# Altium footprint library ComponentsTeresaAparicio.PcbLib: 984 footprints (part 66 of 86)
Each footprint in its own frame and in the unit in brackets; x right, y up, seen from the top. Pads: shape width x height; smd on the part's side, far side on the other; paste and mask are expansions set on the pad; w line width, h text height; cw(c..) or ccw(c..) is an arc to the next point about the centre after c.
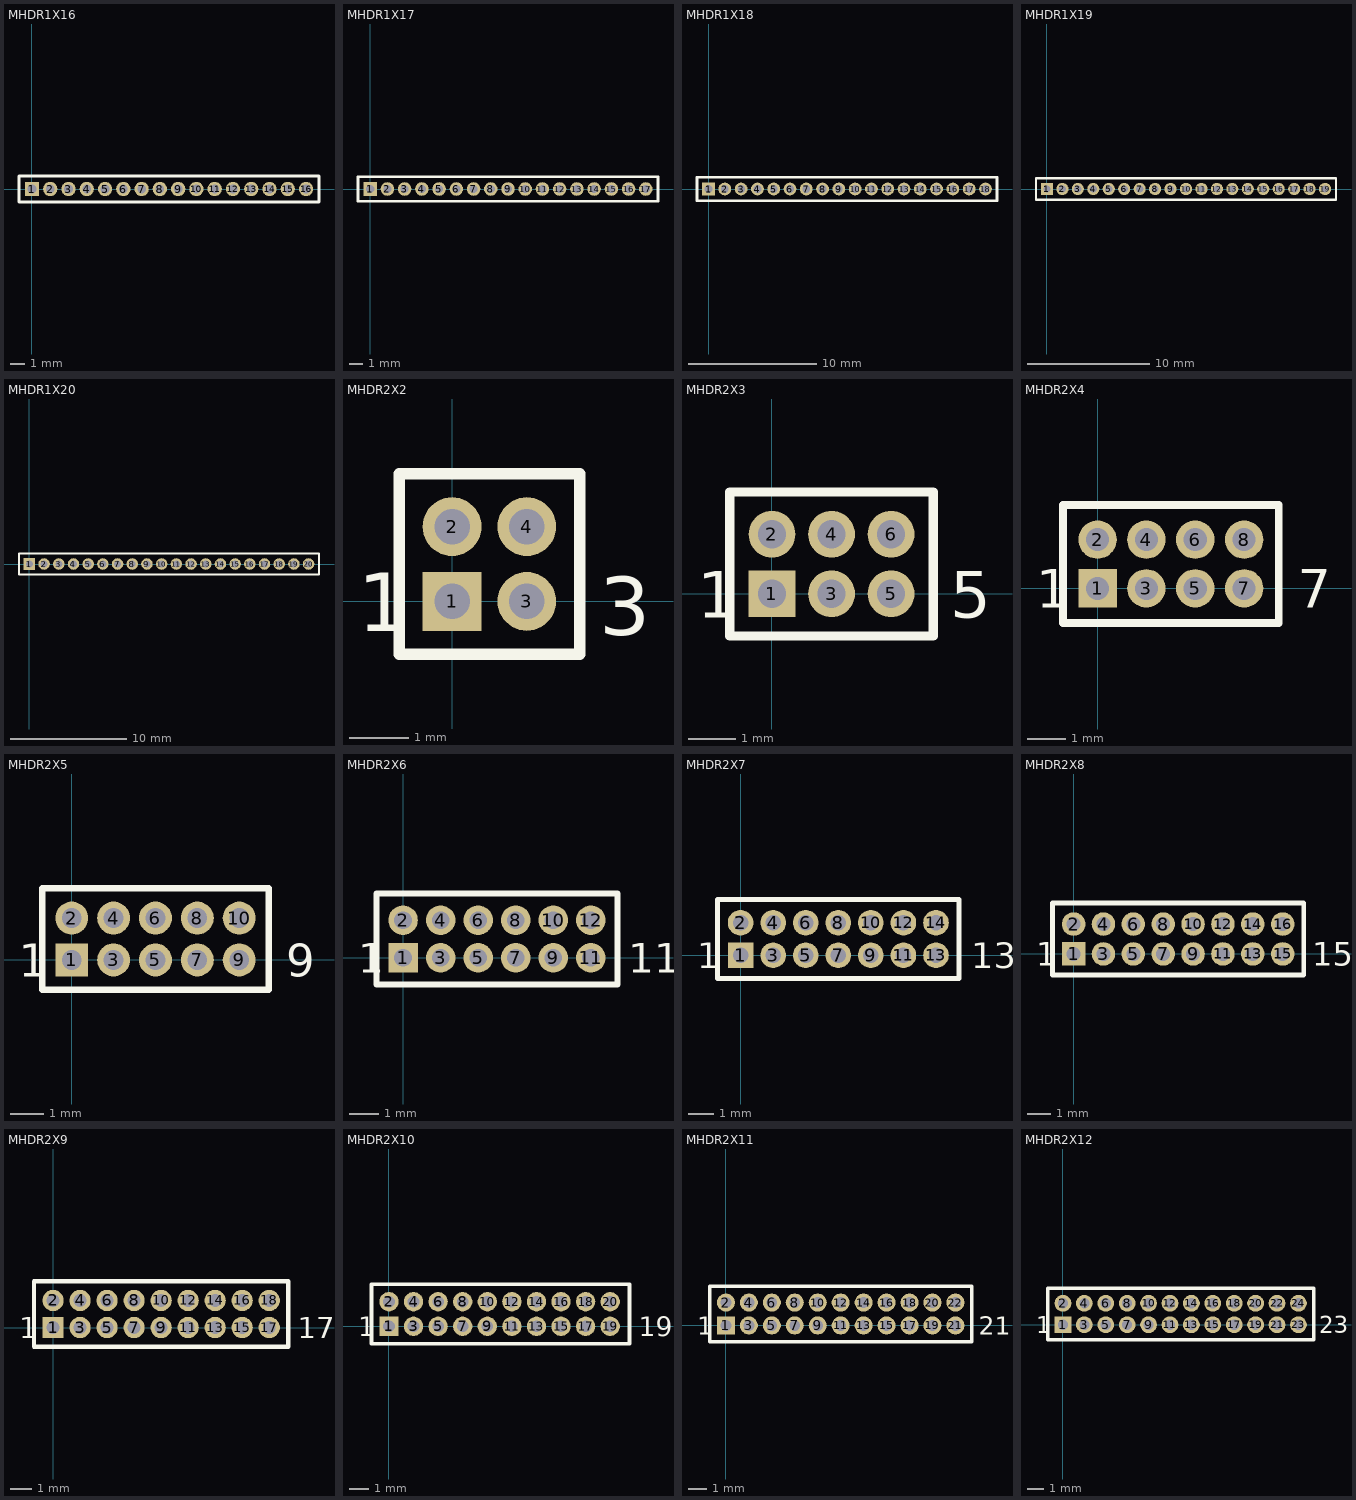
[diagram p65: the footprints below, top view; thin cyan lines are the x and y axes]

## MHDR1X16 [mm] "Connector; Header; 16 Position"
pads (16):
  rect 1x1 hole 0.6: 1(0,0)
  round 1 hole 0.6: 2(1.27,0) 3(2.54,0) 4(3.81,0) 5(5.08,0) 6(6.35,0) 7(7.62,0) 8(8.89,0) 9(10.16,0) 10(11.43,0) 11(12.7,0) 12(13.97,0) 13(15.24,0) 14(16.51,0) 15(17.78,0) 16(19.05,0)
Top Overlay:
  lines w0.2: -0.9,-0.9 19.95,-0.9 19.95,0.9 -0.9,0.9 -0.9,-0.9

## MHDR1X17 [mm] "Connector; Header; 17 Position"
pads (17):
  rect 1x1 hole 0.6: 1(0,0)
  round 1 hole 0.6: 2(1.27,0) 3(2.54,0) 4(3.81,0) 5(5.08,0) 6(6.35,0) 7(7.62,0) 8(8.89,0) 9(10.16,0) 10(11.43,0) 11(12.7,0) 12(13.97,0) 13(15.24,0) 14(16.51,0) 15(17.78,0) 16(19.05,0) 17(20.32,0)
Top Overlay:
  lines w0.2: -0.9,-0.9 -0.9,0.9 21.22,0.9 21.22,-0.9 -0.9,-0.9

## MHDR1X18 [mm] "Connector; Header; 18 Position"
pads (18):
  rect 1x1 hole 0.6: 1(0,0)
  round 1 hole 0.6: 2(1.27,0) 3(2.54,0) 4(3.81,0) 5(5.08,0) 6(6.35,0) 7(7.62,0) 8(8.89,0) 9(10.16,0) 10(11.43,0) 11(12.7,0) 12(13.97,0) 13(15.24,0) 14(16.51,0) 15(17.78,0) 16(19.05,0) 17(20.32,0) 18(21.59,0)
Top Overlay:
  lines w0.2: -0.9,-0.9 22.49,-0.9 22.49,0.9 -0.9,0.9 -0.9,-0.9

## MHDR1X19 [mm] "Connector; Header; 19 Position"
pads (19):
  rect 1x1 hole 0.6: 1(0,0)
  round 1 hole 0.6: 2(1.27,0) 3(2.54,0) 4(3.81,0) 5(5.08,0) 6(6.35,0) 7(7.62,0) 8(8.89,0) 9(10.16,0) 10(11.43,0) 11(12.7,0) 12(13.97,0) 13(15.24,0) 14(16.51,0) 15(17.78,0) 16(19.05,0) 17(20.32,0) 18(21.59,0) 19(22.86,0)
Top Overlay:
  lines w0.2: -0.9,-0.9 23.76,-0.9 23.76,0.9 -0.9,0.9 -0.9,-0.9

## MHDR1X20 [mm] "Connector; Header; 20 Position"
pads (20):
  rect 1x1 hole 0.6: 1(0,0)
  round 1 hole 0.6: 2(1.27,0) 3(2.54,0) 4(3.81,0) 5(5.08,0) 6(6.35,0) 7(7.62,0) 8(8.89,0) 9(10.16,0) 10(11.43,0) 11(12.7,0) 12(13.97,0) 13(15.24,0) 14(16.51,0) 15(17.78,0) 16(19.05,0) 17(20.32,0) 18(21.59,0) 19(22.86,0) 20(24.13,0)
Top Overlay:
  lines w0.2: -0.9,-0.9 -0.9,0.9 25.03,0.9 25.03,-0.9 -0.9,-0.9

## MHDR2X2 [mm] "Connector; Header; 2x2 Position"
pads (4):
  rect 1x1 hole 0.6: 1(0,0)
  round 1 hole 0.6: 2(0,1.27) 3(1.27,0) 4(1.27,1.27)
Top Overlay:
  lines w0.2: -0.9,-0.9 2.17,-0.9 2.17,2.17 -0.9,2.17 -0.9,-0.9
  text "3" at 2.5,-0.578 h1
  text "1" at -1.6,-0.508 h1

## MHDR2X3 [mm] "Connector; Header; 3x2 Position"
pads (6):
  rect 1x1 hole 0.6: 1(0,0)
  round 1 hole 0.6: 2(0,1.27) 3(1.27,0) 4(1.27,1.27) 5(2.54,0) 6(2.54,1.27)
Top Overlay:
  lines w0.2: -0.9,-0.9 3.44,-0.9 3.44,2.17 -0.9,2.17 -0.9,-0.9
  text "1" at -1.6,-0.508 h1
  text "5" at 3.8,-0.508 h1

## MHDR2X4 [mm] "Connector; Header; 4x2 Position"
pads (8):
  rect 1x1 hole 0.6: 1(0,0)
  round 1 hole 0.6: 2(0,1.27) 3(1.27,0) 4(1.27,1.27) 5(2.54,0) 6(2.54,1.27) 7(3.81,0) 8(3.81,1.27)
Top Overlay:
  lines w0.2: -0.9,-0.9 -0.9,2.17 4.71,2.17 4.71,-0.9 -0.9,-0.9
  text "7" at 5.2,-0.508 h1
  text "1" at -1.6,-0.508 h1

## MHDR2X5 [mm] "Connector; Header; 5x2 Position"
pads (10):
  rect 1x1 hole 0.6: 1(0,0)
  round 1 hole 0.6: 2(0,1.27) 3(1.27,0) 4(1.27,1.27) 5(2.54,0) 6(2.54,1.27) 7(3.81,0) 8(3.81,1.27) 9(5.08,0) 10(5.08,1.27)
Top Overlay:
  lines w0.2: -0.9,-0.9 -0.9,2.17 5.98,2.17 5.98,-0.9 -0.9,-0.9
  text "9" at 6.5,-0.508 h1
  text "1" at -1.6,-0.508 h1

## MHDR2X6 [mm] "Connector; Header; 6x2 Position"
pads (12):
  rect 1x1 hole 0.6: 1(0,0)
  round 1 hole 0.6: 2(0,1.27) 3(1.27,0) 4(1.27,1.27) 5(2.54,0) 6(2.54,1.27) 7(3.81,0) 8(3.81,1.27) 9(5.08,0) 10(5.08,1.27) 11(6.35,0) 12(6.35,1.27)
Top Overlay:
  lines w0.2: -0.9,-0.9 7.25,-0.9 7.25,2.17 -0.9,2.17 -0.9,-0.9
  text "1" at -1.524,-0.508 h1
  text "11" at 7.62,-0.508 h1

## MHDR2X7 [mm] "Connector; Header; 7x2 Position"
pads (14):
  rect 1x1 hole 0.6: 1(0,0)
  round 1 hole 0.6: 2(0,1.27) 3(1.27,0) 4(1.27,1.27) 5(2.54,0) 6(2.54,1.27) 7(3.81,0) 8(3.81,1.27) 9(5.08,0) 10(5.08,1.27) 11(6.35,0) 12(6.35,1.27) 13(7.62,0) 14(7.62,1.27)
Top Overlay:
  lines w0.2: -0.9,-0.9 -0.9,2.17 8.52,2.17 8.52,-0.9 -0.9,-0.9
  text "13" at 9,-0.508 h1
  text "1" at -1.7,-0.508 h1

## MHDR2X8 [mm] "Connector; Header; 8x2 Position"
pads (16):
  rect 1x1 hole 0.6: 1(0,0)
  round 1 hole 0.6: 2(0,1.27) 3(1.27,0) 4(1.27,1.27) 5(2.54,0) 6(2.54,1.27) 7(3.81,0) 8(3.81,1.27) 9(5.08,0) 10(5.08,1.27) 11(6.35,0) 12(6.35,1.27) 13(7.62,0) 14(7.62,1.27) 15(8.89,0) 16(8.89,1.27)
Top Overlay:
  lines w0.2: -0.9,-0.9 9.79,-0.9 9.79,2.17 -0.9,2.17 -0.9,-0.9
  text "1" at -1.6,-0.508 h1
  text "15" at 10.16,-0.508 h1

## MHDR2X9 [mm] "Connector; Header; 9x2 Position"
pads (18):
  rect 1x1 hole 0.6: 1(0,0)
  round 1 hole 0.6: 2(0,1.27) 3(1.27,0) 4(1.27,1.27) 5(2.54,0) 6(2.54,1.27) 7(3.81,0) 8(3.81,1.27) 9(5.08,0) 10(5.08,1.27) 11(6.35,0) 12(6.35,1.27) 13(7.62,0) 14(7.62,1.27) 15(8.89,0) 16(8.89,1.27) 17(10.16,0) 18(10.16,1.27)
Top Overlay:
  lines w0.2: -0.9,-0.9 11.06,-0.9 11.06,2.17 -0.9,2.17 -0.9,-0.9
  text "1" at -1.6,-0.508 h1
  text "17" at 11.5,-0.508 h1

## MHDR2X10 [mm] "Connector; Header; 10x2 Position"
pads (20):
  rect 1x1 hole 0.6: 1(0,0)
  round 1 hole 0.6: 2(0,1.27) 3(1.27,0) 4(1.27,1.27) 5(2.54,0) 6(2.54,1.27) 7(3.81,0) 8(3.81,1.27) 9(5.08,0) 10(5.08,1.27) 11(6.35,0) 12(6.35,1.27) 13(7.62,0) 14(7.62,1.27) 15(8.89,0) 16(8.89,1.27) 17(10.16,0) 18(10.16,1.27) 19(11.43,0) 20(11.43,1.27)
Top Overlay:
  lines w0.2: -0.9,-0.9 -0.9,2.17 12.43,2.17 12.43,-0.9 -0.9,-0.9
  text "19" at 12.9,-0.508 h1
  text "1" at -1.6,-0.508 h1

## MHDR2X11 [mm] "Connector; Header; 11x2 Position"
pads (22):
  rect 1x1 hole 0.6: 1(0,0)
  round 1 hole 0.6: 2(0,1.27) 3(1.27,0) 4(1.27,1.27) 5(2.54,0) 6(2.54,1.27) 7(3.81,0) 8(3.81,1.27) 9(5.08,0) 10(5.08,1.27) 11(6.35,0) 12(6.35,1.27) 13(7.62,0) 14(7.62,1.27) 15(8.89,0) 16(8.89,1.27) 17(10.16,0) 18(10.16,1.27) 19(11.43,0) 20(11.43,1.27) 21(12.7,0) 22(12.7,1.27)
Top Overlay:
  lines w0.2: -0.9,-0.9 13.6,-0.9 13.6,2.17 -0.9,2.17 -0.9,-0.9
  text "1" at -1.6,-0.508 h1
  text "21" at 14,-0.508 h1

## MHDR2X12 [mm] "Connector; Header; 12x2 Position"
pads (24):
  rect 1x1 hole 0.6: 1(0,0)
  round 1 hole 0.6: 2(0,1.27) 3(1.27,0) 4(1.27,1.27) 5(2.54,0) 6(2.54,1.27) 7(3.81,0) 8(3.81,1.27) 9(5.08,0) 10(5.08,1.27) 11(6.35,0) 12(6.35,1.27) 13(7.62,0) 14(7.62,1.27) 15(8.89,0) 16(8.89,1.27) 17(10.16,0) 18(10.16,1.27) 19(11.43,0) 20(11.43,1.27) 21(12.7,0) 22(12.7,1.27) 23(13.97,0) 24(13.97,1.27)
Top Overlay:
  lines w0.2: -0.9,-0.9 14.87,-0.9 14.87,2.17 -0.9,2.17 -0.9,-0.9
  text "1" at -1.6,-0.508 h1
  text "23" at 15.2,-0.508 h1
